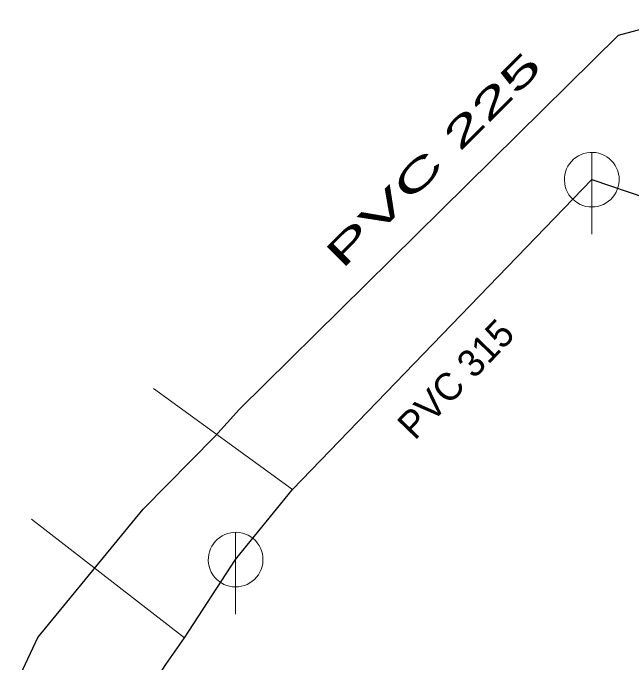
# Model space of a CAD drawing. Extents: x -659250 to -657316, y -997555 to -993684.
# Drawn here: x -658624.56 to -658601.96, y -995198.48 to -995174.75 of the extents above; entities that cross this region are included whole.
import ezdxf

# ---------------------------------------------------------------- set-up
doc = ezdxf.new("R2010")
doc.units = 0
doc.header["$LTSCALE"] = 0.4
doc.layers.add('1', color=7, linetype='Continuous')
for name, color, linetype, lineweight in [('11', 7, 'Continuous', 13), ('14', 7, 'Continuous', 25), ('17', 7, 'Continuous', 25), ('22', 7, 'Continuous', 13)]:
    doc.layers.add(name, color=color, linetype=linetype, lineweight=lineweight)

msp = doc.modelspace()

# ---------------------------------------------------------------- linework, layer by layer
at = {"layer": '11'}
for p, q in [((-658619.423, -995188.483), (-658614.342, -995192.174)), ((-658623.884, -995193.254), (-658618.294, -995197.598))]:
    msp.add_line(p, q, dxfattribs=at)
at = {"layer": '14'}
msp.add_line((-658603.399, -995180.842), (-658583.91, -995187.37), dxfattribs=at)
for points in [[(-658616.42, -995194.739), (-658614.342, -995192.173), (-658603.399, -995180.842)], [(-658622.92, -995204.671), (-658618.978, -995198.574), (-658618.294, -995197.598), (-658616.42, -995194.739)]]:
    msp.add_lwpolyline(points, dxfattribs=at)
at = {"layer": '17'}
msp.add_lwpolyline([(-658633.311, -995219.004), (-658632.3, -995216.89), (-658625.646, -995201.835), (-658623.653, -995197.583), (-658619.796, -995192.896), (-658617.175, -995190.239), (-658616.274, -995189.232), (-658602.428, -995175.557), (-658599.375, -995174.746), (-658589.094, -995179.075), (-658583.371, -995184.746)], dxfattribs=at)
at = {"layer": '22'}
for p, q in [((-658603.399, -995182.842), (-658603.398, -995179.842)), ((-658616.42, -995196.74), (-658616.419, -995193.74))]:
    msp.add_line(p, q, dxfattribs=at)
for points in [[(-658602.399, -995180.842), (-658602.404, -995180.733), (-658602.422, -995180.625), (-658602.452, -995180.519), (-658602.492, -995180.418), (-658602.544, -995180.321), (-658602.606, -995180.231), (-658602.678, -995180.148), (-658602.758, -995180.074), (-658602.846, -995180.008), (-658602.94, -995179.953), (-658603.04, -995179.908), (-658603.145, -995179.875), (-658603.252, -995179.853), (-658603.361, -995179.843), (-658603.471, -995179.845), (-658603.579, -995179.859), (-658603.686, -995179.884), (-658603.789, -995179.921), (-658603.887, -995179.97), (-658603.979, -995180.028), (-658604.065, -995180.097), (-658604.142, -995180.174), (-658604.211, -995180.26), (-658604.27, -995180.352), (-658604.318, -995180.45), (-658604.355, -995180.553), (-658604.381, -995180.66), (-658604.395, -995180.768), (-658604.398, -995180.878), (-658604.388, -995180.987), (-658604.367, -995181.094), (-658604.333, -995181.198), (-658604.289, -995181.298), (-658604.234, -995181.393), (-658604.168, -995181.481), (-658604.094, -995181.561), (-658604.011, -995181.633), (-658603.921, -995181.695), (-658603.825, -995181.747), (-658603.723, -995181.788), (-658603.618, -995181.818), (-658603.51, -995181.836), (-658603.4, -995181.842), (-658603.291, -995181.836), (-658603.183, -995181.818), (-658603.078, -995181.789), (-658602.976, -995181.748), (-658602.879, -995181.696), (-658602.789, -995181.634), (-658602.706, -995181.563), (-658602.631, -995181.483), (-658602.566, -995181.395), (-658602.51, -995181.301), (-658602.466, -995181.201), (-658602.432, -995181.097), (-658602.41, -995180.989), (-658602.4, -995180.88)], [(-658615.42, -995194.74), (-658615.425, -995194.631), (-658615.443, -995194.523), (-658615.473, -995194.417), (-658615.513, -995194.316), (-658615.565, -995194.219), (-658615.627, -995194.129), (-658615.699, -995194.046), (-658615.779, -995193.972), (-658615.867, -995193.906), (-658615.961, -995193.851), (-658616.061, -995193.806), (-658616.166, -995193.773), (-658616.273, -995193.751), (-658616.382, -995193.741), (-658616.492, -995193.743), (-658616.6, -995193.757), (-658616.707, -995193.782), (-658616.81, -995193.819), (-658616.908, -995193.868), (-658617, -995193.926), (-658617.086, -995193.995), (-658617.163, -995194.072), (-658617.232, -995194.158), (-658617.291, -995194.25), (-658617.339, -995194.348), (-658617.376, -995194.451), (-658617.402, -995194.558), (-658617.416, -995194.666), (-658617.419, -995194.776), (-658617.409, -995194.885), (-658617.388, -995194.992), (-658617.354, -995195.096), (-658617.31, -995195.196), (-658617.255, -995195.291), (-658617.189, -995195.379), (-658617.115, -995195.459), (-658617.032, -995195.531), (-658616.942, -995195.593), (-658616.846, -995195.645), (-658616.744, -995195.686), (-658616.639, -995195.716), (-658616.531, -995195.734), (-658616.421, -995195.74), (-658616.312, -995195.734), (-658616.204, -995195.716), (-658616.099, -995195.687), (-658615.997, -995195.646), (-658615.9, -995195.594), (-658615.81, -995195.532), (-658615.727, -995195.461), (-658615.652, -995195.381), (-658615.587, -995195.293), (-658615.531, -995195.199), (-658615.487, -995195.099), (-658615.453, -995194.995), (-658615.431, -995194.887), (-658615.421, -995194.778)]]:
    msp.add_lwpolyline(points, close=True, dxfattribs=at)

# ---------------------------------------------------------------- texts
at = {"layer": '1', "width": 1.95}
msp.add_text('PVC 225 ', height=1, rotation=45, dxfattribs=at).set_placement((-658612.533, -995184.153))
at = {"layer": '1'}
msp.add_text('PVC 315 ', height=1, rotation=46, dxfattribs=at).set_placement((-658609.873, -995190.404))

doc.saveas('drawing.dxf')
